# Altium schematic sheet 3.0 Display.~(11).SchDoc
size A4; SheetNumber: 3; SheetTotal: 7
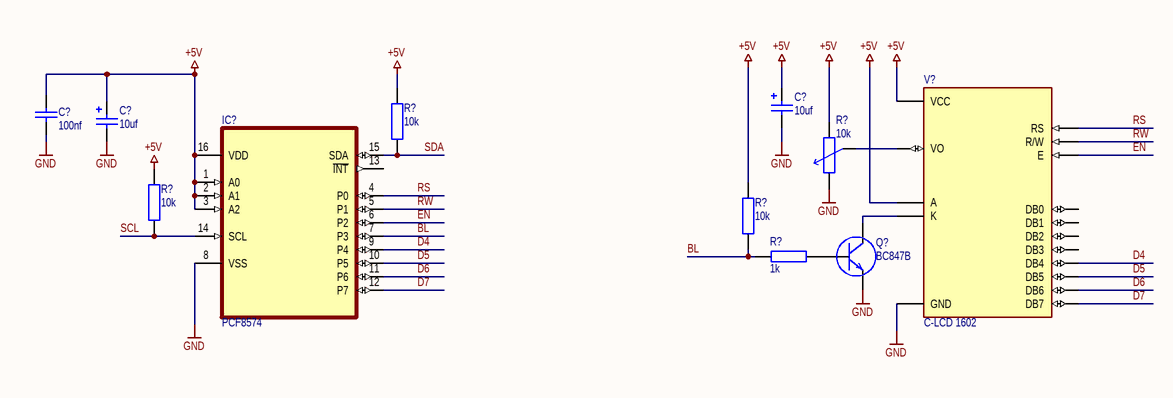
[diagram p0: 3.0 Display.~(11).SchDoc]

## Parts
(Parts that share a designator on the sheet are numbered #1, #2 ... from top to bottom, then left to right.)
C?#1  10uf  [C_SMD_C-TYP]
C?#2  10uf  [C_SMD_D-TYP]
C?#3  100nf  [C_SMD_0805]
IC?  PCF8574  [SO-16]
Q?  BC847B  [SOT-23]
R?#1  10k  [R_THT_POT-TP-.2/.1]
R?#2  10k  [R_SMD_0805]
R?#3  10k  [R_SMD_0805]
R?#4  10k  [R_SMD_0805]
R?#5  1k  [R_SMD_0805]
V?  C-LCD 1602  [V_MODULE_LCD-16X2]

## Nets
+5V: C?#1.1 C?#2.1 C?#3.1 IC?.1(A0) IC?.2(A1) IC?.3(A2) IC?.16(VDD) R?#1.1 R?#2.2 R?#3.2 R?#4.2 V?.2(VCC) V?.15(A)
GND: C?#1.2 C?#2.2 C?#3.2 IC?.8(VSS) Q?.2(E) R?#1.2 V?.1(GND)
BL: IC?.7(P3) R?#4.1 R?#5.1
D4: IC?.9(P4) V?.11(DB4)
D5: IC?.10(P5) V?.12(DB5)
D6: IC?.11(P6) V?.13(DB6)
D7: IC?.12(P7) V?.14(DB7)
EN: IC?.6(P2) V?.6(E)
RS: IC?.4(P0) V?.4(RS)
RW: IC?.5(P1) V?.5(R/W)
SCL: IC?.14(SCL) R?#3.1
SDA: IC?.15(SDA) R?#2.1
NetQ?_1: Q?.1(B) R?#5.2
NetQ?_3: Q?.3(C) V?.16(K)
NetR?#1_3: R?#1.3 V?.3(VO)

Not connected (* = marked no-connect by the designer): IC? 13(~{INT}); V? 7(DB0) 8(DB1) 9(DB2) 10(DB3)

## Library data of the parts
C?#1 C?#2 = C_SMD_ELK: SMD Elektrolytkondensator
C?#3 = C_SMD_KO: Kondensator SMD Universal, Keramik, Folie, usw.
IC? = IC_PCF8574: I/O Expander
Q? = Q_SMD_NPN: NPN Transistor
R?#1 = R_THT_Potentiometer: Potentiometer; Set Position: 0.5
R?#2-R?#5 = R_SMD_Widerstand: Widerstand SMD
V? = V_C-LCD-1602: LC-Display; MF: Gravitech; MP: LCD-16X2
